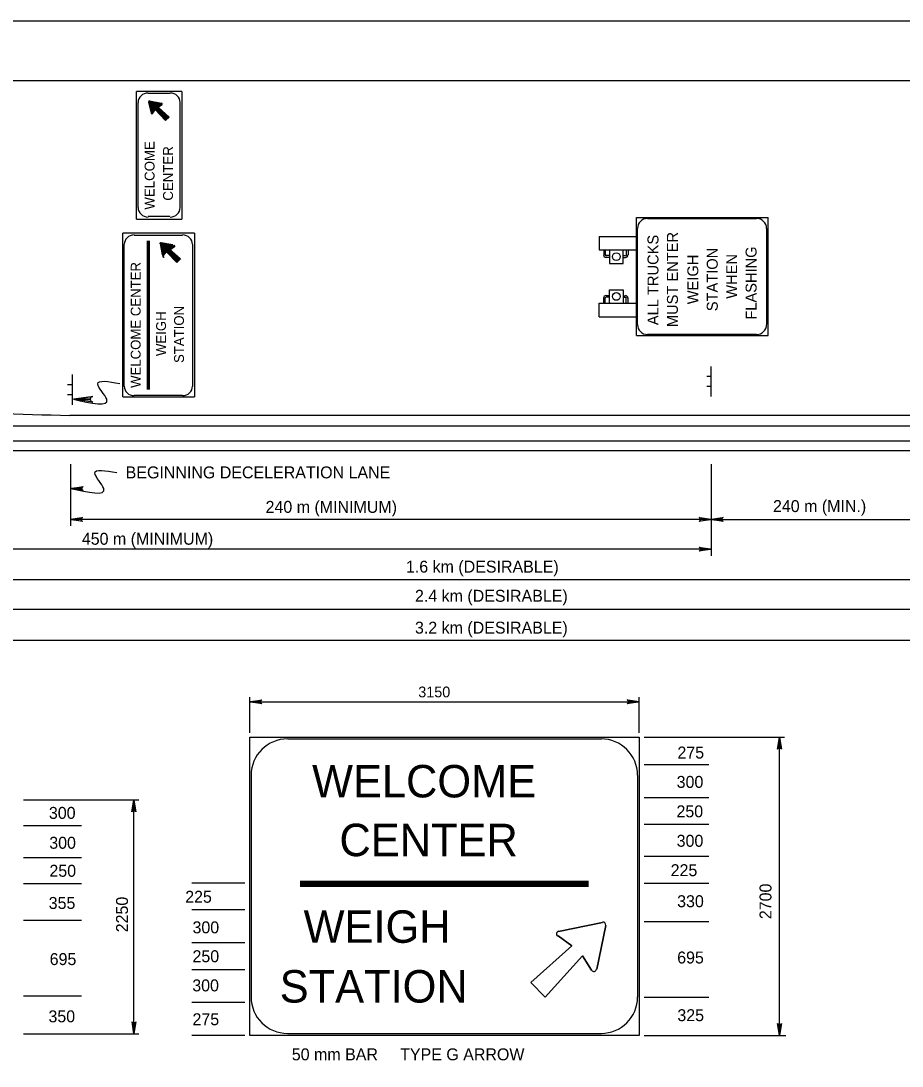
# Model space of a CAD drawing. Extents: x 638689 to 652291, y 298458 to 299646.
# Drawn here: x 651743.8 to 651965, y 299383.4 to 299645.7 of the extents above; entities that cross this region are included whole.
import ezdxf

# ---------------------------------------------------------------- set-up
doc = ezdxf.new("R2010")
doc.units = 0
for name, color, linetype in [('1', 7, 'Continuous'), ('2', 7, 'Continuous'), ('3', 7, 'Continuous'), ('PLT-BNDY', 7, 'Continuous')]:
    doc.layers.add(name, color=color, linetype=linetype)

# ---------------------------------------------------------------- blocks, each defined once
blk = doc.blocks.new('RARROW')
at = {"layer": '3'}
blk.add_lwpolyline([(-2.2695, 0.285), (-2.184875, 0.12075), (0, 0), (-2.2695, 0.285), (-2.38575, 0.384625), (0, 0), (-2.183125, -0.108), (-2.262875, -0.2705), (0, 0), (-2.38575, -0.379125), (-2.262875, -0.2705)], dxfattribs=at)

msp = doc.modelspace()

# ---------------------------------------------------------------- linework, layer by layer
at = {"layer": '1'}
msp.add_line((651426.31, 299630.75), (652212.31, 299630.75), dxfattribs=at)
at = {"layer": '2'}
for p, q in [((651772.81, 299596), (651772.81, 299628)), ((651784.19, 299628), (651772.81, 299628)), ((651784.19, 299628), (651784.19, 299596)), ((651773.19, 299598.87), (651773.19, 299625.25)), ((651775.69, 299627.62), (651781.19, 299627.62)), ((651775.81, 299625.62), (651775.81, 299625.62)), ((651775.81, 299625.37), (651776.44, 299622.62)), ((651779.06, 299625), (651776.06, 299625.62)), ((651783.69, 299625.25), (651783.69, 299598.87)), ((651776.81, 299622.5), (651777.44, 299623.5)), ((651777.44, 299623.5), (651777.44, 299623.5)), ((651777.44, 299623.5), (651780.06, 299620.75)), ((651777.81, 299623.75), (651777.81, 299623.75)), ((651778.19, 299624.12), (651779.19, 299624.75)), ((651778.19, 299624.12), (651779.19, 299624.75)), ((651778.19, 299624.12), (651778.19, 299624.12)), ((651780.94, 299621.62), (651778.19, 299624.12)), ((651779.56, 299625), (651779.56, 299625)), ((651776.56, 299622.12), (651776.56, 299622.12)), ((651780.06, 299620.75), (651780.94, 299621.62)), ((651780.06, 299620.75), (651780.06, 299620.75)), ((651780.94, 299621.62), (651780.94, 299621.62)), ((651781.19, 299596.62), (651775.69, 299596.62)), ((651898.31, 299566.75), (651898.31, 299596.37)), ((651898.31, 299596.37), (651931.31, 299596.37)), ((651931.31, 299566.75), (651931.31, 299596.37)), ((651772.81, 299596), (651784.19, 299596)), ((651901.06, 299596.12), (651928.44, 299596.12)), ((651769.31, 299551.37), (651769.31, 299592.5)), ((651787.31, 299592.5), (651769.31, 299592.5)), ((651772.19, 299592), (651784.31, 299592)), ((651787.31, 299592.5), (651787.31, 299551.37)), ((651888.94, 299591.62), (651888.94, 299588.25)), ((651888.94, 299591.62), (651898.31, 299591.62)), ((651898.56, 299569.5), (651898.56, 299593.62)), ((651930.94, 299593.62), (651930.94, 299569.5)), ((651769.69, 299554), (651769.69, 299589.62)), ((651775.56, 299553.25), (651775.56, 299590.5)), ((651775.69, 299553.25), (651775.69, 299590.5)), ((651775.81, 299553.25), (651775.81, 299590.5)), ((651775.94, 299553.25), (651775.94, 299590.5)), ((651776.06, 299553.25), (651776.06, 299590.5)), ((651778.56, 299590.12), (651778.56, 299590.12)), ((651778.69, 299589.87), (651779.31, 299587)), ((651781.94, 299589.5), (651778.94, 299590)), ((651780.94, 299588.5), (651782.06, 299589.12)), ((651780.94, 299588.5), (651782.06, 299589.12)), ((651781.19, 299588.25), (651782.31, 299589.12)), ((651782.44, 299589.37), (651782.44, 299589.37)), ((651786.81, 299589.62), (651786.81, 299554)), ((651779.44, 299586.5), (651779.44, 299586.5)), ((651779.56, 299586.87), (651780.31, 299587.75)), ((651780.31, 299587.75), (651780.31, 299587.75)), ((651780.31, 299587.75), (651782.94, 299585.12)), ((651780.44, 299587.5), (651780.44, 299587.5)), ((651780.56, 299588.12), (651780.56, 299588.12)), ((651780.81, 299587.87), (651780.81, 299587.87)), ((651780.94, 299588.5), (651780.94, 299588.5)), ((651783.81, 299586), (651780.94, 299588.5)), ((651781.19, 299588.25), (651781.19, 299588.25)), ((651782.94, 299585.12), (651783.81, 299586)), ((651783.81, 299586), (651783.81, 299586)), ((651888.94, 299588.25), (651891.56, 299588.25)), ((651890.06, 299588.25), (651890.06, 299587)), ((651890.44, 299588.25), (651890.44, 299587)), ((651891.56, 299586.87), (651890.69, 299586.87)), ((651891.56, 299586.37), (651890.69, 299586.37)), ((651891.56, 299588.25), (651891.56, 299584.87)), ((651891.56, 299588.25), (651898.31, 299588.25)), ((651894.94, 299584.87), (651894.94, 299588.25)), ((651894.94, 299586.87), (651895.44, 299586.87)), ((651894.94, 299586.37), (651895.44, 299586.37)), ((651895.69, 299588.25), (651895.69, 299587)), ((651896.19, 299588.25), (651896.19, 299587)), ((651782.94, 299585.12), (651782.94, 299585.12)), ((651891.56, 299584.87), (651894.94, 299584.87)), ((651891.56, 299574.87), (651891.56, 299578.25)), ((651891.56, 299578.25), (651894.94, 299578.25)), ((651894.94, 299578.25), (651894.94, 299574.87)), ((651890.06, 299574.87), (651890.06, 299576.25)), ((651890.44, 299574.87), (651890.44, 299576.25)), ((651891.56, 299576.75), (651890.69, 299576.75)), ((651891.56, 299576.37), (651890.69, 299576.37)), ((651894.94, 299576.75), (651895.44, 299576.75)), ((651894.94, 299576.37), (651895.44, 299576.37)), ((651895.69, 299574.87), (651895.69, 299576.25)), ((651896.19, 299574.87), (651896.19, 299576.25)), ((651888.94, 299571.5), (651888.94, 299574.87)), ((651888.94, 299574.87), (651891.56, 299574.87)), ((651891.56, 299574.87), (651898.31, 299574.87)), ((651888.94, 299571.5), (651898.31, 299571.5)), ((651898.31, 299566.75), (651931.31, 299566.75)), ((651928.44, 299567), (651901.06, 299567)), ((651917.06, 299551.5), (651917.06, 299559)), ((651756.69, 299549.37), (651756.69, 299557)), ((651917.06, 299556.5), (651915.94, 299556.5)), ((651756.69, 299554.37), (651755.44, 299554.37)), ((651756.69, 299551.87), (651755.44, 299551.87)), ((651917.06, 299554), (651915.94, 299554)), ((651769.31, 299551.37), (651787.31, 299551.37)), ((651784.31, 299551.75), (651772.19, 299551.75)), ((651756.06, 299546.75), (651756.06, 299546.75)), ((651756.06, 299546.75), (652211.31, 299546.75)), ((651429.31, 299544.12), (652211.31, 299544.12)), ((651429.31, 299540.37), (652211.31, 299540.37)), ((651429.31, 299537.87), (652211.31, 299537.87)), ((651756.19, 299534.5), (651756.19, 299519)), ((651917.06, 299534.5), (651917.06, 299511.5)), ((651917.06, 299520.62), (651756.19, 299520.62)), ((651917.06, 299520.62), (651978.67, 299520.62)), ((651917.06, 299513.12), (651680.69, 299513.12)), ((651680.69, 299505.5), (652031.94, 299505.5)), ((652084.69, 299498), (651680.69, 299498)), ((652137.56, 299490.25), (651680.69, 299490.25)), ((651801.23, 299467.07), (651801.23, 299475.95)), ((651898.98, 299467.07), (651898.98, 299475.95)), ((651801.23, 299474.82), (651898.98, 299474.82)), ((651801.23, 299465.95), (651898.98, 299465.95)), ((651801.23, 299391.07), (651801.23, 299465.95)), ((651889.48, 299465.45), (651810.73, 299465.45)), ((651898.98, 299465.95), (651898.98, 299391.07)), ((651900.23, 299465.95), (651910.23, 299465.95)), ((651900.23, 299465.95), (651910.23, 299465.95)), ((651906.98, 299465.95), (651935.48, 299465.95)), ((651934.23, 299391.07), (651934.23, 299465.95)), ((651900.23, 299459.07), (651916.42, 299459.07)), ((651801.6, 299456.32), (651801.6, 299400.7)), ((651898.6, 299400.7), (651898.6, 299456.32)), ((651744.45, 299450.23), (651773.4, 299450.23)), ((651772.15, 299391.48), (651772.15, 299450.23)), ((651900.23, 299450.82), (651916.42, 299450.82)), ((651744.45, 299443.73), (651759, 299443.73)), ((651900.23, 299444.07), (651916.42, 299444.07)), ((651744.45, 299435.73), (651759, 299435.73)), ((651900.23, 299436.07), (651916.42, 299436.07)), ((651744.45, 299429.23), (651759, 299429.23)), ((651799.98, 299429.32), (651786.67, 299429.32)), ((651813.85, 299429.82), (651886.23, 299429.82)), ((651813.85, 299429.57), (651886.23, 299429.57)), ((651813.85, 299429.32), (651886.23, 299429.32)), ((651813.85, 299429.07), (651886.23, 299429.07)), ((651813.85, 299428.82), (651886.23, 299428.82)), ((651813.85, 299428.57), (651886.23, 299428.57)), ((651900.23, 299429.32), (651916.42, 299429.32)), ((651799.98, 299422.57), (651786.67, 299422.57)), ((651744.45, 299419.98), (651759, 299419.98)), ((651889.73, 299419.45), (651878.73, 299417.2)), ((651878.73, 299417.2), (651889.73, 299419.45)), ((651888.35, 299407.7), (651890.6, 299418.7)), ((651890.6, 299418.7), (651888.35, 299407.7)), ((651890.85, 299419.7), (651890.85, 299419.7)), ((651900.23, 299419.7), (651916.42, 299419.7)), ((651877.1, 299416.95), (651877.1, 299416.95)), ((651878.6, 299416.07), (651882.1, 299413.57)), ((651882.1, 299413.57), (651878.6, 299416.07)), ((651799.98, 299414.32), (651786.67, 299414.32)), ((651882.1, 299413.57), (651871.73, 299404.32)), ((651871.73, 299404.32), (651882.1, 299413.57)), ((651882.1, 299413.57), (651871.73, 299404.32)), ((651871.73, 299404.32), (651882.1, 299413.57)), ((651882.1, 299413.57), (651882.1, 299413.57)), ((651882.1, 299413.57), (651882.1, 299413.57)), ((651875.35, 299400.7), (651884.73, 299411.07)), ((651884.73, 299411.07), (651875.35, 299400.7)), ((651883.35, 299412.45), (651883.35, 299412.45)), ((651883.35, 299412.45), (651883.35, 299412.45)), ((651884.73, 299411.07), (651884.73, 299411.07)), ((651884.73, 299411.07), (651884.73, 299411.07)), ((651884.73, 299411.07), (651886.98, 299407.45)), ((651886.98, 299407.45), (651884.73, 299411.07)), ((651799.98, 299407.57), (651786.67, 299407.57)), ((651887.85, 299406.07), (651887.85, 299406.07)), ((651871.73, 299404.32), (651871.73, 299404.32)), ((651871.73, 299404.32), (651871.73, 299404.32)), ((651871.73, 299404.32), (651875.35, 299400.7)), ((651875.35, 299400.7), (651871.73, 299404.32)), ((651744.45, 299400.98), (651759, 299400.98)), ((651875.35, 299400.7), (651875.35, 299400.7)), ((651875.35, 299400.7), (651875.35, 299400.7)), ((651900.23, 299400.7), (651916.42, 299400.7)), ((651799.98, 299399.32), (651786.67, 299399.32)), ((651744.45, 299391.48), (651773.4, 299391.48)), ((651799.98, 299391.07), (651786.67, 299391.07)), ((651898.98, 299391.07), (651801.23, 299391.07)), ((651810.73, 299391.57), (651889.48, 299391.57)), ((651900.23, 299391.07), (651935.76, 299391.07))]:
    msp.add_line(p, q, dxfattribs=at)
for points in [[(651780.81, 299621.62), (651780.06, 299620.87), (651777.44, 299623.62), (651776.81, 299622.62), (651776.69, 299622.62), (651776.56, 299622.62), (651775.94, 299625.37), (651776.06, 299625.5), (651779.19, 299624.87), (651778.06, 299624.12), (651780.81, 299621.62), (651780.06, 299621), (651777.44, 299623.62), (651776.69, 299622.75), (651776.69, 299622.62), (651776.06, 299625.37), (651779.06, 299624.87), (651778.06, 299624.12), (651780.69, 299621.62), (651780.19, 299621.12), (651777.44, 299623.75), (651776.69, 299622.87), (651776.19, 299625.25), (651778.81, 299624.75), (651777.81, 299624.12), (651780.56, 299621.62), (651780.19, 299621.25), (651777.44, 299623.75), (651776.81, 299623), (651776.31, 299625.12), (651778.56, 299624.75), (651777.81, 299624.12), (651780.44, 299621.62), (651780.19, 299621.37), (651777.44, 299623.87), (651776.94, 299623.25), (651776.56, 299625), (651778.44, 299624.62), (651777.56, 299624.12), (651780.31, 299621.62), (651780.19, 299621.62), (651777.44, 299624), (651776.94, 299623.5), (651776.69, 299624.87), (651778.19, 299624.62), (651777.56, 299624.12), (651780.31, 299621.75), (651780.19, 299621.62), (651780.19, 299621.5), (651777.44, 299624.12), (651780.19, 299621.75), (651780.06, 299621.62), (651777.44, 299624.12), (651777.06, 299623.75), (651776.81, 299624.75), (651777.94, 299624.5), (651777.19, 299624), (651776.94, 299624.62), (651777.81, 299624.5), (651777.31, 299624.12), (651777.19, 299624.62), (651777.56, 299624.5), (651777.31, 299624.37), (651777.31, 299624.5), (651777.44, 299624.5)], [(651783.69, 299586.12), (651782.94, 299585.37), (651780.31, 299587.87), (651779.56, 299587), (651779.44, 299586.87), (651779.31, 299587), (651778.81, 299589.87), (651778.94, 299590), (651782.06, 299589.25), (651780.81, 299588.5), (651783.69, 299586.12), (651782.94, 299585.5), (651780.31, 299588), (651779.56, 299587), (651779.56, 299587), (651778.94, 299589.87), (651781.81, 299589.25), (651780.81, 299588.37), (651783.56, 299586.12), (651782.94, 299585.62), (651780.31, 299588.12), (651779.56, 299587.12), (651779.06, 299589.75), (651781.69, 299589.25), (651780.56, 299588.37), (651783.44, 299586.12), (651783.06, 299585.75), (651780.31, 299588.12), (651779.69, 299587.37), (651779.19, 299589.62), (651781.31, 299589.12), (651780.56, 299588.37), (651783.31, 299586.12), (651783.06, 299585.87), (651780.31, 299588.25), (651779.81, 299587.62), (651779.31, 299589.5), (651781.06, 299589.12), (651780.44, 299588.37), (651783.19, 299586.12), (651783.06, 299586), (651780.31, 299588.37), (651779.81, 299587.87), (651779.56, 299589.37), (651780.94, 299589.12), (651780.31, 299588.37), (651783.06, 299586.12), (651783.06, 299586), (651783.06, 299586), (651780.31, 299588.37), (651783.06, 299586.12), (651782.94, 299586), (651780.31, 299588.37), (651779.94, 299588), (651779.69, 299589.25), (651780.69, 299589), (651780.06, 299588.25), (651779.81, 299589.12), (651780.56, 299589), (651780.06, 299588.5), (651779.94, 299589), (651780.31, 299589), (651780.19, 299588.75), (651780.06, 299589), (651780.31, 299588.87)], [(651761.44, 299550.25), (651761.31, 299550.62), (651756.94, 299550.75), (651761.44, 299550.25), (651761.81, 299550), (651756.94, 299550.75), (651761.31, 299551), (651761.44, 299551.37), (651756.94, 299550.75), (651761.81, 299551.5), (651761.44, 299551.37)]]:
    msp.add_lwpolyline(points, dxfattribs=at)
for centre in [(651893.25, 299586.57), (651893.25, 299576.58)]:
    msp.add_circle(centre, 0.977, dxfattribs=at)
for centre, radius, start, end in [((651901.02, 299593.67), 2.47, 90, 180), ((651928.47, 299593.67), 2.47, 0, 90), ((651890.65, 299586.99), 0.613, 180, 270), ((651890.65, 299586.99), 0.223, 180, 270), ((651895.53, 299586.99), 0.223, 270, 0), ((651895.53, 299586.99), 0.613, 270, 0), ((651890.65, 299576.16), 0.613, 90, 180), ((651890.65, 299576.16), 0.223, 90, 180), ((651895.53, 299576.16), 0.613, 0, 90), ((651895.53, 299576.16), 0.223, 0, 90), ((651901.02, 299569.49), 2.47, 180, 270), ((651928.47, 299569.49), 2.47, 270, 0), ((651789.98, 300979.53), 1433.22, 265.6447, 268.64351), ((651810.69, 299456.38), 9.14, 90, 180), ((651889.42, 299456.38), 9.14, 0, 90), ((651889.89, 299418.84), 0.686, 348.2602, 101.7398), ((651889.89, 299418.84), 0.686, 348.2602, 101.7398), ((651878.88, 299416.55), 0.686, 101.7398, 236.6838), ((651878.88, 299416.55), 0.686, 101.7398, 236.6838), ((651887.6, 299407.83), 0.686, 213.3162, 348.2602), ((651887.6, 299407.83), 0.686, 213.3162, 348.2602), ((651810.69, 299400.72), 9.14, 180, 270), ((651889.42, 299400.72), 9.14, 270, 0)]:
    msp.add_arc(centre, radius, start, end, dxfattribs=at)
for centre, major_axis, start_param, end_param in [((651775.68, 299625.28), (-2.49, 0), 4.712389, 6.283185), ((651776.02, 299625.48), (-0.189, 0), 4.50749, 6.488084), ((651781.26, 299625.28), (2.49, 0), 0, 1.570796), ((651779.05, 299624.88), (0.189, 0), 5.293867, 7.649083), ((651776.65, 299622.6), (0.189, 0), 3.346491, 5.701707), ((651775.68, 299598.88), (-2.49, 0), 0, 1.570796), ((651781.26, 299598.88), (2.49, 0), 4.712389, 6.283185), ((651772.19, 299589.66), (-2.47, 0), 4.712389, 6.283185), ((651784.36, 299589.66), (2.47, 0), 0, 1.570796), ((651778.84, 299589.85), (-0.189, 0), 4.50749, 6.488084), ((651778.86, 299589.83), (-0.21, 0), 4.50749, 6.488084), ((651781.87, 299589.26), (0.189, 0), 5.293867, 7.649083), ((651782.23, 299589.17), (0.21, 0), 5.293867, 7.649083), ((651779.47, 299586.98), (0.189, 0), 3.346491, 5.701707), ((651779.56, 299586.63), (0.21, 0), 3.346491, 5.701707), ((651772.19, 299554.02), (-2.47, 0), 0, 1.570796), ((651784.36, 299554.02), (2.47, 0), 4.712389, 6.283185)]:
    msp.add_ellipse(centre, major_axis=major_axis, ratio=0.95, start_param=start_param, end_param=end_param, dxfattribs=at)
for points in [[(651756.94, 299550.75), (651765.31, 299550.75), (651763.06, 299554.62), (651768.56, 299554.75)], [(651756.19, 299528.37), (651764.56, 299528.37), (651762.31, 299532.25), (651767.81, 299532.37)]]:
    msp.add_spline(points, degree=3, dxfattribs=at)
at = {"layer": 'PLT-BNDY'}
msp.add_lwpolyline([(651386.31, 299645.75), (652227.31, 299645.75), (652227.31, 299051.75), (651386.31, 299051.75)], close=True, dxfattribs=at)

# ---------------------------------------------------------------- block references
at = {"layer": '2', "xscale": 1.2574347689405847, "yscale": 1.3092961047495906}
for p, rotation in [((651756.36, 299528.37), 180), ((651756.19, 299520.62), 180), ((651917.06, 299520.62), 180), ((651801.23, 299474.82), 180), ((651934.23, 299465.95), 89.99999999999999), ((651772.15, 299450.23), 89.99999999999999), ((651772.15, 299391.48), -90.00000000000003), ((651934.23, 299391.07), -90.00000000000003)]:
    msp.add_blockref('RARROW', p, dxfattribs=dict(at, rotation=rotation))
for p in [(651917.06, 299520.62), (651917.06, 299513.12), (651898.98, 299474.82)]:
    msp.add_blockref('RARROW', p, dxfattribs=at)

# ---------------------------------------------------------------- texts
at = {"layer": '2'}
for s, height, p in [('WELCOME', 2.488, (651777.31, 299598.37)), ('CENTER', 2.488, (651781.94, 299600.62)), ('ALL TRUCKS', 2.749, (651903.81, 299569.37)), ('MUST ENTER', 2.749, (651908.69, 299568.87)), ('STATION', 2.749, (651918.69, 299572.87)), ('FLASHING', 2.749, (651928.44, 299570.75)), ('WEIGH', 2.749, (651913.81, 299574.62)), ('WHEN', 2.749, (651923.56, 299576)), ('WELCOME CENTER', 2.4728, (651773.81, 299553.62)), ('STATION', 2.473, (651784.69, 299559.87)), ('WEIGH', 2.473, (651780.19, 299561.62)), (' 2700', 3, (651932.18, 299419.14)), ('2250', 3, (651770.64, 299416.96))]:
    msp.add_text(s, height=height, rotation=90, dxfattribs=at).set_placement(p)
for s, height, p in [('BEGINNING DECELERATION LANE', 3, (651770.06, 299530.91)), ('240 m (MIN.)', 3, (651932.56, 299522.45)), ('240 m (MINIMUM)', 3, (651805.19, 299522.25)), ('450 m (MINIMUM)', 3, (651759.06, 299514.25)), (' 1.6 km (DESIRABLE)', 3, (651839.31, 299507.25)), ('2.4 km (DESIRABLE)', 3, (651842.69, 299499.93)), ('3.2 km (DESIRABLE)', 3, (651842.69, 299491.93)), ('3150', 2.7, (651843.51, 299475.94)), ('275', 3, (651908.57, 299460.58)), ('WELCOME', 8.143, (651816.85, 299450.82)), ('300', 3, (651908.38, 299453.21)), ('300', 3, (651750.79, 299445.43)), ('250', 3, (651908.33, 299445.82)), ('CENTER', 8.143, (651823.73, 299436.07)), ('300', 3, (651750.88, 299437.93)), ('300', 3, (651908.38, 299438.43)), ('250', 3, (651750.92, 299430.9)), (' 225', 3, (651905.76, 299431.05)), ('355', 3, (651750.74, 299422.82)), (' 225', 3, (651783.89, 299424.38)), ('330', 3, (651908.5, 299423.26)), ('WEIGH', 8.143, (651814.73, 299414.32)), ('300', 3, (651786.84, 299416.7)), ('695', 3, (651750.99, 299408.73)), ('250', 3, (651786.84, 299409.45)), ('695', 3, (651908.51, 299409.13)), ('STATION', 8.143, (651808.73, 299399.32)), ('300', 3, (651786.78, 299402.13)), ('350', 3, (651750.68, 299394.36)), ('325', 3, (651908.56, 299394.65)), ('275', 3, (651786.84, 299393.63)), ('50 mm BAR     TYPE G ARROW', 3, (651811.77, 299384.82))]:
    msp.add_text(s, height=height, dxfattribs=at).set_placement(p)

doc.saveas('drawing.dxf')
